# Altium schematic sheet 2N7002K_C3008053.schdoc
size 127 x 101 mm
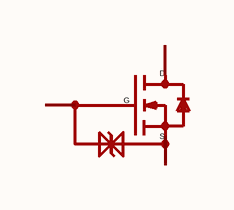
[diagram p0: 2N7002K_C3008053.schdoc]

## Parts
Q?  2n7002k_c3008053  [SOT-23-3_L2.9-W1.3-P1.90-LS2.4-BL-1]  (value not drawn)

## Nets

Not connected (* = marked no-connect by the designer): Q? 1(G) 2(S) 3(D)

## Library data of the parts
Q? = 2n7002k_c3008053: 数量:1个N沟道;漏源电压(Vdss):60V;连续漏极电流(Id):300mA;导通电阻(RDS(on)):2.2Ω@10V;耗散功率(Pd):350mW;阈值电压(Vgs(th)):2.5V;; Manufacturer: MSKSEMI(美森科); AddInBom: yes; ModelId: 115ef394a879442d90491e6127930138; ModelName: SOT-23-3_L2.9-W1.3-P1.90-LS2.4; ModelTransform: 114.173,94.488,0,0,0,0,0,0,0; Number: 1个N沟道; Drain to Source Voltage: 60V; Current - Continuous Drain(Id): 300mA; Pd - Power Dissipation: 350mW; Gate Threshold Voltage (Vgs(th)): 2.5V; Gate Charge(Qg): 5.6nC@10V; Input Capacitance(Ciss): 38pF; Reverse Transfer Capacitance (Crss@Vds): 12pF; Output Capacitance(Coss): 26pF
